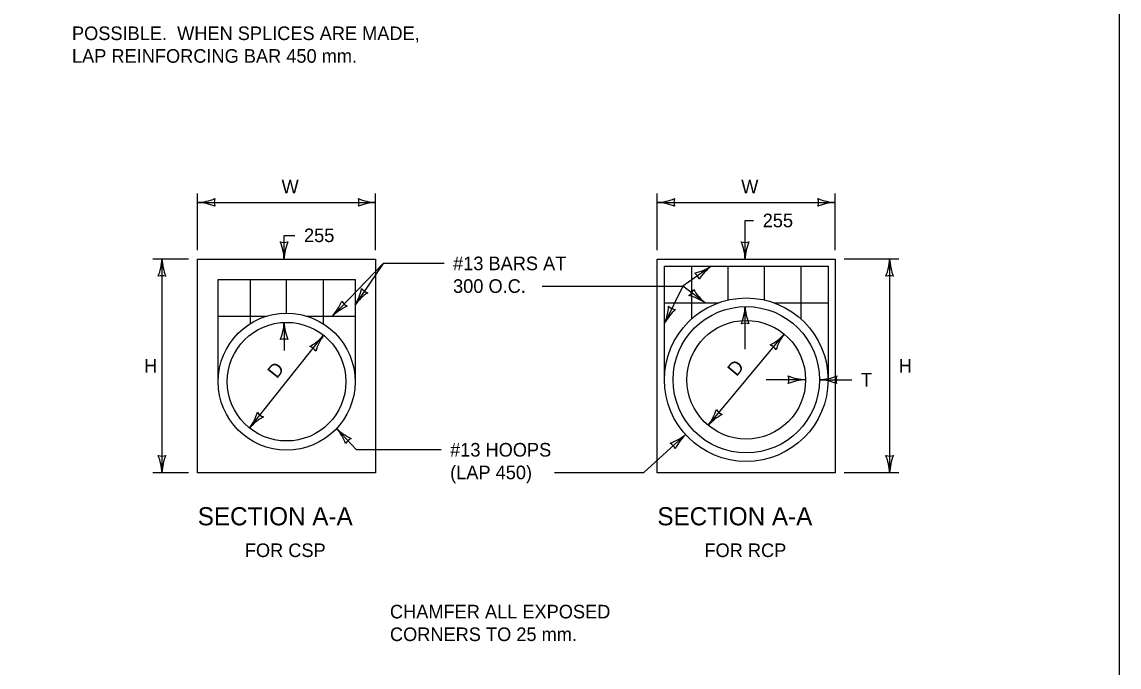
# Model space of a CAD drawing. Extents: x 49991.4 to 50043, y 49987.6 to 50011.4.
# Drawn here: x 50011.911 to 50016.75, y 49993.468 to 49996.314 of the extents above; entities that cross this region are included whole.
import ezdxf

# ---------------------------------------------------------------- set-up
doc = ezdxf.new("R2010")
doc.units = 0
for name, color, linetype in [('Level 1', 7, 'Continuous'), ('Level 2', 7, 'Continuous'), ('Level 3', 7, 'Continuous')]:
    doc.layers.add(name, color=color, linetype=linetype)

msp = doc.modelspace()

# ---------------------------------------------------------------- linework, layer by layer
at = {"layer": 'Level 1'}
for p, q in [((50014.7132, 49995.2678), (50015.4983, 49995.2678)), ((50014.7132, 49994.3256), (50014.7132, 49995.2678)), ((50015.4983, 49995.2678), (50015.4983, 49994.3256)), ((50014.7451, 49995.236), (50015.4665, 49995.236)), ((50014.7451, 49994.7356), (50014.7451, 49995.236)), ((50014.8639, 49995.236), (50014.8639, 49995.0032)), ((50015.0247, 49995.236), (50015.0247, 49995.0871)), ((50015.1855, 49995.236), (50015.1855, 49995.0874)), ((50015.3462, 49995.236), (50015.3462, 49995.0045)), ((50015.4665, 49995.236), (50015.4665, 49994.7356)), ((50012.7768, 49995.1771), (50013.3806, 49995.1771)), ((50012.7768, 49994.727), (50012.7768, 49995.1771)), ((50012.9179, 49995.1771), (50012.9179, 49994.9825)), ((50013.0787, 49995.0289), (50013.0787, 49995.1771)), ((50013.2395, 49995.1771), (50013.2395, 49994.9825)), ((50013.3806, 49995.1771), (50013.3806, 49994.727)), ((50014.7451, 49995.0752), (50014.9843, 49995.0752)), ((50015.2273, 49995.0752), (50015.4665, 49995.0752)), ((50012.7768, 49995.0164), (50012.9927, 49995.0164)), ((50013.1647, 49995.0164), (50013.3806, 49995.0164)), ((50015.4983, 49994.3256), (50014.7132, 49994.3256))]:
    msp.add_line(p, q, dxfattribs=at)
for points in [[(49999.3835, 49998.9992), (50016.7501, 49998.9992), (50016.7501, 49987.7988), (49999.3835, 49987.7988)], [(50012.6861, 49995.2678), (50013.4713, 49995.2678), (50013.4713, 49994.3256), (50012.6861, 49994.3256)]]:
    msp.add_lwpolyline(points, close=True, dxfattribs=at)
for centre, radius in [((50015.1058, 49994.7356), 0.3607), ((50013.0787, 49994.727), 0.3019), ((50015.1058, 49994.7356), 0.3228), ((50013.0787, 49994.727), 0.2617), ((50015.1058, 49994.7356), 0.2617)]:
    msp.add_circle(centre, radius, dxfattribs=at)
at = {"layer": 'Level 3'}
for p, q in [((50012.6861, 49995.3078), (50012.6861, 49995.5576)), ((50013.4713, 49995.3078), (50013.4713, 49995.5576)), ((50014.7132, 49995.3078), (50014.7132, 49995.5576)), ((50015.4983, 49995.3078), (50015.4983, 49995.5576)), ((50012.6861, 49995.5176), (50013.4713, 49995.5176)), ((50014.7132, 49995.5176), (50015.4983, 49995.5176)), ((50015.1007, 49995.2678), (50015.1007, 49995.4381)), ((50015.1007, 49995.4381), (50015.1384, 49995.4381)), ((50013.0676, 49995.2678), (50013.0676, 49995.3725)), ((50013.0676, 49995.3725), (50013.1154, 49995.3725)), ((50012.6461, 49995.2678), (50012.489, 49995.2678)), ((50012.529, 49995.2678), (50012.529, 49994.3256)), ((50015.7783, 49995.2678), (50015.5383, 49995.2678)), ((50015.7383, 49995.2678), (50015.7383, 49994.3256)), ((50013.5052, 49995.2487), (50013.2808, 49995.0164)), ((50013.5052, 49995.2487), (50013.3806, 49995.0659)), ((50013.7729, 49995.2487), (50013.5052, 49995.2487)), ((50014.9505, 49995.236), (50014.8258, 49995.1488)), ((50014.2062, 49995.1487), (50014.8258, 49995.1488)), ((50014.8258, 49995.1488), (50014.7451, 49994.9843)), ((50014.9242, 49995.0752), (50014.8258, 49995.1488)), ((50015.1007, 49994.871), (50015.1007, 49995.0584)), ((50013.0676, 49994.9885), (50013.0676, 49994.8647)), ((50012.9155, 49994.5224), (50013.2419, 49994.9316)), ((50014.9384, 49994.5344), (50015.2731, 49994.9368)), ((50015.3675, 49994.7356), (50015.1941, 49994.7356)), ((50015.4286, 49994.7356), (50015.5712, 49994.7356)), ((50013.3876, 49994.4266), (50013.2993, 49994.5209)), ((50014.6543, 49994.3266), (50014.8378, 49994.4941)), ((50013.7598, 49994.4266), (50013.3876, 49994.4266)), ((50012.6461, 49994.3256), (50012.489, 49994.3256)), ((50014.2606, 49994.3266), (50014.6543, 49994.3266)), ((50015.7783, 49994.3256), (50015.5383, 49994.3256))]:
    msp.add_line(p, q, dxfattribs=at)
for centre, radius, start, end in [((50012.6746, 49995.7503), 0.233, 272.8273, 292.0772), ((50012.6769, 49995.2955), 0.2223, 67.456, 87.6395), ((50012.8143, 49995.5176), 0.0548, 162.1388, 197.8612), ((50013.4805, 49995.7398), 0.2223, 247.456, 267.6395), ((50013.3431, 49995.5176), 0.0548, 342.1388, 17.8612), ((50013.4828, 49995.2849), 0.233, 92.8273, 112.0772), ((50014.7017, 49995.7503), 0.233, 272.8273, 292.0772), ((50014.704, 49995.2955), 0.2223, 67.456, 87.6395), ((50014.8414, 49995.5176), 0.0548, 162.1388, 197.8612), ((50015.5075, 49995.7398), 0.2223, 247.456, 267.6395), ((50015.3701, 49995.5176), 0.0548, 342.1388, 17.8612), ((50015.5098, 49995.2849), 0.233, 92.8273, 112.0772), ((50013.0676, 49995.396), 0.0548, 252.1388, 287.8612), ((50012.8349, 49995.2563), 0.233, 2.8273, 22.0772), ((50013.2897, 49995.2587), 0.2223, 157.456, 177.6395), ((50015.1007, 49995.396), 0.0548, 252.1388, 287.8612), ((50014.868, 49995.2563), 0.233, 2.8273, 22.0772), ((50015.3228, 49995.2587), 0.2223, 157.456, 177.6395), ((50012.3069, 49995.277), 0.2223, 337.456, 357.6395), ((50012.7617, 49995.2793), 0.233, 182.8273, 202.0772), ((50015.5162, 49995.277), 0.2223, 337.456, 357.6395), ((50015.971, 49995.2793), 0.233, 182.8273, 202.0772), ((50014.8307, 49995.4233), 0.2223, 282.4274, 302.6109), ((50015.0933, 49995.0519), 0.233, 127.7987, 147.0485), ((50012.529, 49995.1396), 0.0548, 72.1388, 107.8612), ((50014.8454, 49995.1625), 0.0548, 17.1102, 52.8325), ((50015.7383, 49995.1396), 0.0548, 72.1388, 107.8612), ((50013.1818, 49995.1875), 0.233, 328.555, 347.8049), ((50013.559, 49994.9333), 0.2223, 123.1837, 143.3672), ((50013.4528, 49995.1719), 0.0548, 217.8665, 253.5889), ((50014.8215, 49995.152), 0.0548, 305.349, 341.0713), ((50015.0646, 49995.2476), 0.2223, 210.6662, 230.8497), ((50013.1054, 49995.1698), 0.233, 318.8188, 338.0686), ((50013.3699, 49995.1086), 0.0548, 208.1303, 243.8526), ((50014.794, 49994.882), 0.233, 56.0375, 75.2873), ((50013.4342, 49994.8555), 0.2223, 113.4475, 133.631), ((50014.5311, 49995.0765), 0.233, 336.6993, 355.9492), ((50014.9405, 49994.8783), 0.2223, 131.328, 151.5115), ((50014.8016, 49995.0994), 0.0548, 226.0108, 261.7332), ((50014.8786, 49995.0676), 0.2223, 337.456, 357.6395), ((50015.3334, 49995.0699), 0.233, 182.8273, 202.0772), ((50012.8455, 49994.9976), 0.2223, 337.456, 357.6395), ((50013.3003, 49995), 0.233, 182.8273, 202.0772), ((50015.1007, 49994.9302), 0.0548, 72.1388, 107.8612), ((50013.0739, 49995.0773), 0.2223, 298.8783, 319.0618), ((50013.431, 49994.7955), 0.233, 144.2496, 163.4994), ((50015.1082, 49995.0859), 0.2223, 297.7037, 317.8872), ((50015.4594, 49994.7969), 0.233, 143.075, 162.3249), ((50013.0676, 49994.8603), 0.0548, 72.1388, 107.8612), ((50013.1619, 49994.8314), 0.0548, 33.5611, 69.2834), ((50015.1911, 49994.8383), 0.0548, 32.3865, 68.1089), ((50015.3767, 49994.9578), 0.2223, 247.456, 267.6395), ((50015.2393, 49994.7356), 0.0548, 342.1388, 17.8612), ((50015.379, 49994.5029), 0.233, 92.8273, 112.0772), ((50015.4176, 49994.9684), 0.233, 272.7247, 291.9746), ((50015.4191, 49994.5135), 0.2223, 67.3534, 87.5369), ((50015.5568, 49994.7354), 0.0548, 162.0362, 197.7586), ((50012.7264, 49994.6586), 0.233, 324.2496, 343.4994), ((50012.9955, 49994.6227), 0.0548, 213.5611, 249.2834), ((50014.7521, 49994.6744), 0.233, 323.075, 342.3249), ((50015.1033, 49994.3853), 0.2223, 117.7037, 137.8872), ((50015.0204, 49994.633), 0.0548, 212.3865, 248.1089), ((50013.0835, 49994.3768), 0.2223, 118.8783, 139.0618), ((50013.1309, 49994.3757), 0.2223, 20.5942, 40.7777), ((50013.4612, 49994.6884), 0.233, 225.9655, 245.2153), ((50014.6948, 49994.6643), 0.2223, 289.8633, 310.0468), ((50015.0032, 49994.3301), 0.233, 135.2346, 154.4844), ((50013.387, 49994.4273), 0.0548, 115.277, 150.9993), ((50014.7431, 49994.4077), 0.0548, 24.5461, 60.2684), ((50012.529, 49994.4538), 0.0548, 252.1388, 287.8612), ((50012.2963, 49994.3141), 0.233, 2.8273, 22.0772), ((50012.7511, 49994.3165), 0.2223, 157.456, 177.6395), ((50015.7383, 49994.4538), 0.0548, 252.1388, 287.8612), ((50015.5056, 49994.3141), 0.233, 2.8273, 22.0772), ((50015.9604, 49994.3165), 0.2223, 157.456, 177.6395)]:
    msp.add_arc(centre, radius, start, end, dxfattribs=at)

# ---------------------------------------------------------------- texts
at = {"layer": 'Level 2'}
for s, height, p in [('POSSIBLE.  WHEN SPLICES ARE MADE,', 0.06, (50012.1321, 49996.2338)), ('LAP REINFORCING BAR 450 mm.', 0.06, (50012.1321, 49996.1338)), ('W', 0.06, (50013.0565, 49995.5576)), ('W', 0.06, (50015.0836, 49995.5576)), ('255', 0.06, (50015.1784, 49995.4081)), ('255', 0.06, (50013.1554, 49995.3425)), ('#13 BARS AT ', 0.06, (50013.8129, 49995.2187)), ('300 O.C.', 0.06, (50013.8129, 49995.1187)), ('H', 0.06, (50012.4498, 49994.7667)), ('H', 0.06, (50015.7783, 49994.7667)), ('T', 0.06, (50015.6112, 49994.7056)), ('#13 HOOPS', 0.06, (50013.7998, 49994.3966)), ('(LAP 450)', 0.06, (50013.7998, 49994.2966)), ('SECTION A-A', 0.08, (50012.6867, 49994.0933)), ('SECTION A-A', 0.08, (50014.7138, 49994.0933)), ('FOR CSP', 0.06, (50012.8944, 49993.9533)), ('FOR RCP', 0.06, (50014.9215, 49993.9533)), ('CHAMFER ALL EXPOSED', 0.06, (50013.5345, 49993.6827)), ('CORNERS TO 25 mm.', 0.06, (50013.5345, 49993.5827))]:
    msp.add_text(s, height=height, dxfattribs=at).set_placement(p)
for rotation, p in [(51.4222, (50013.0358, 49994.7374)), (50.2561, (50015.0631, 49994.7469))]:
    msp.add_text('D', height=0.06, rotation=rotation, dxfattribs=at).set_placement(p)

doc.saveas('drawing.dxf')
